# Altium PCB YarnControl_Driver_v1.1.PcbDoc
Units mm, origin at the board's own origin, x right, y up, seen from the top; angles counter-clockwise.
Board outline 80 x 60 mm, 2 copper layers (Top Layer, Bottom Layer); 133 components, 96 nets, 439 pads, 185 vias.
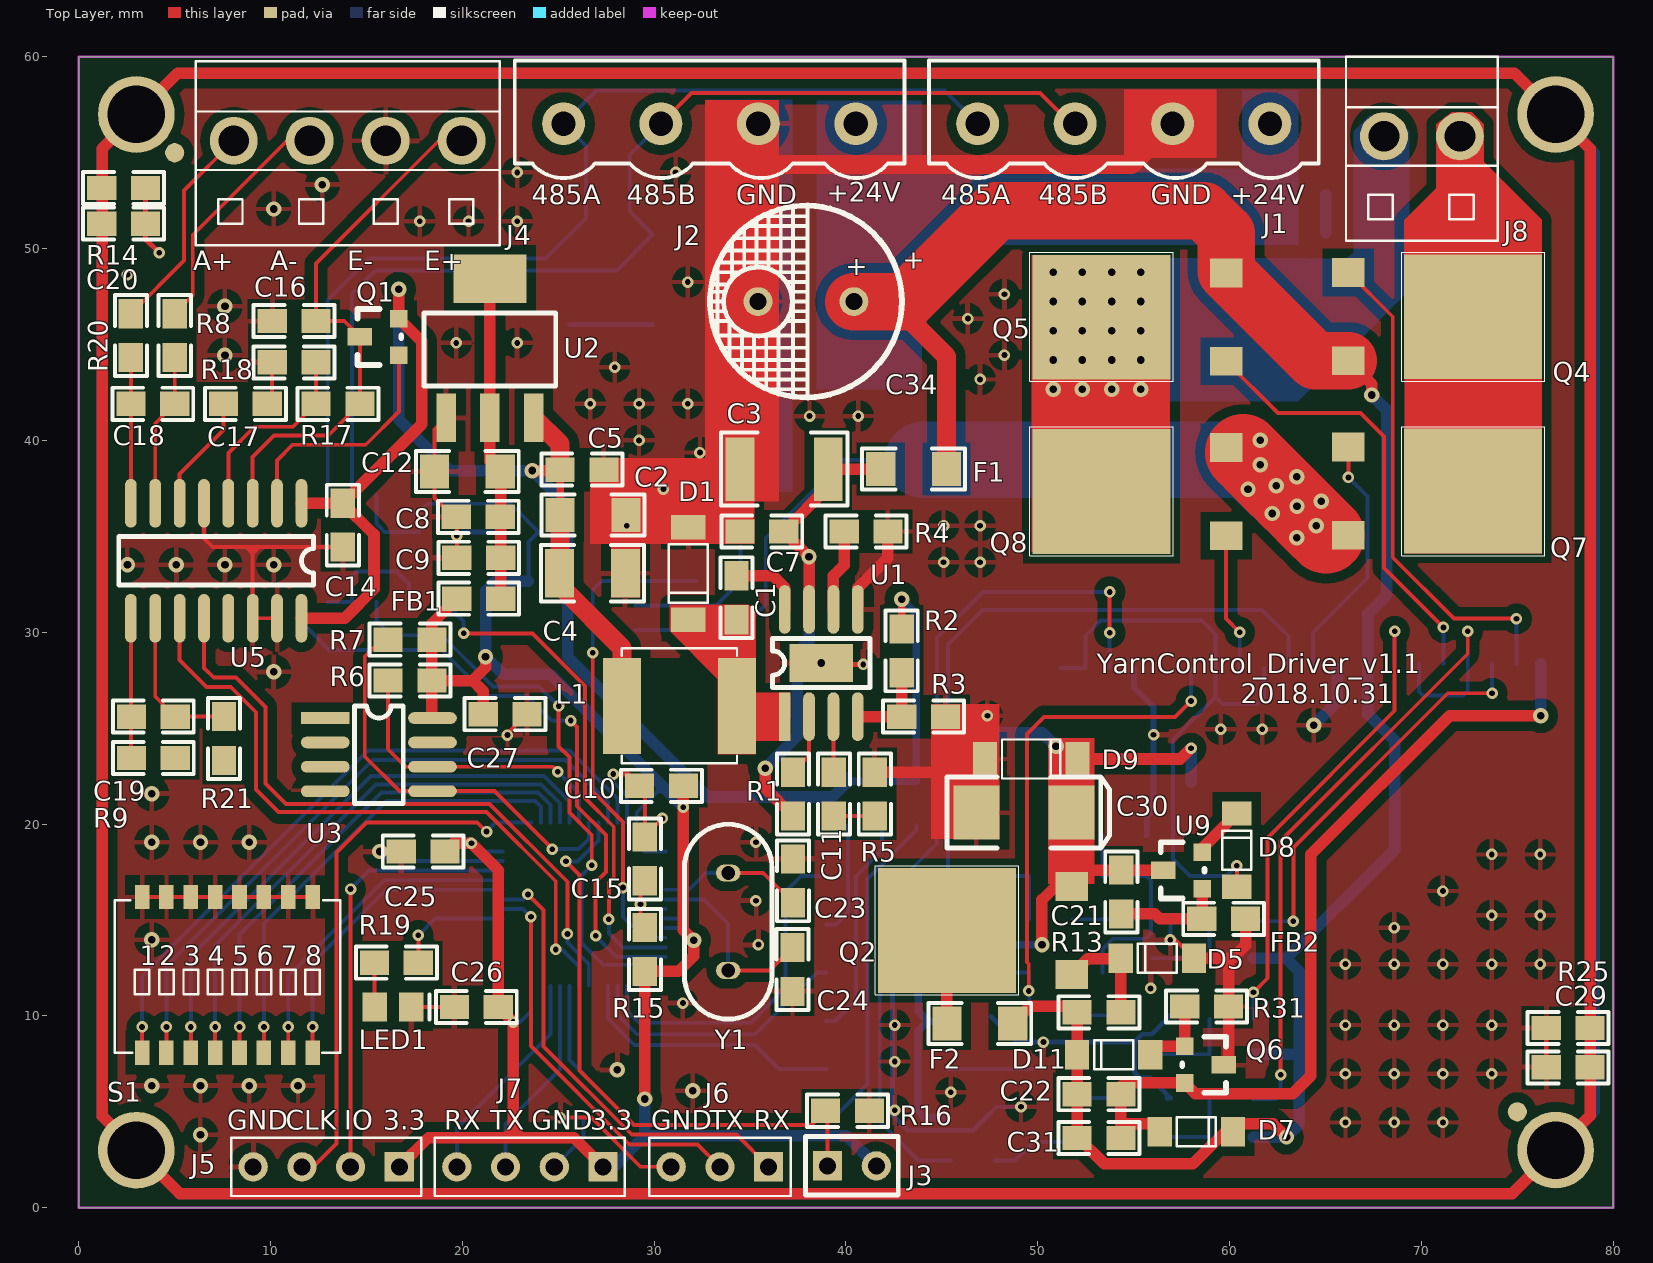
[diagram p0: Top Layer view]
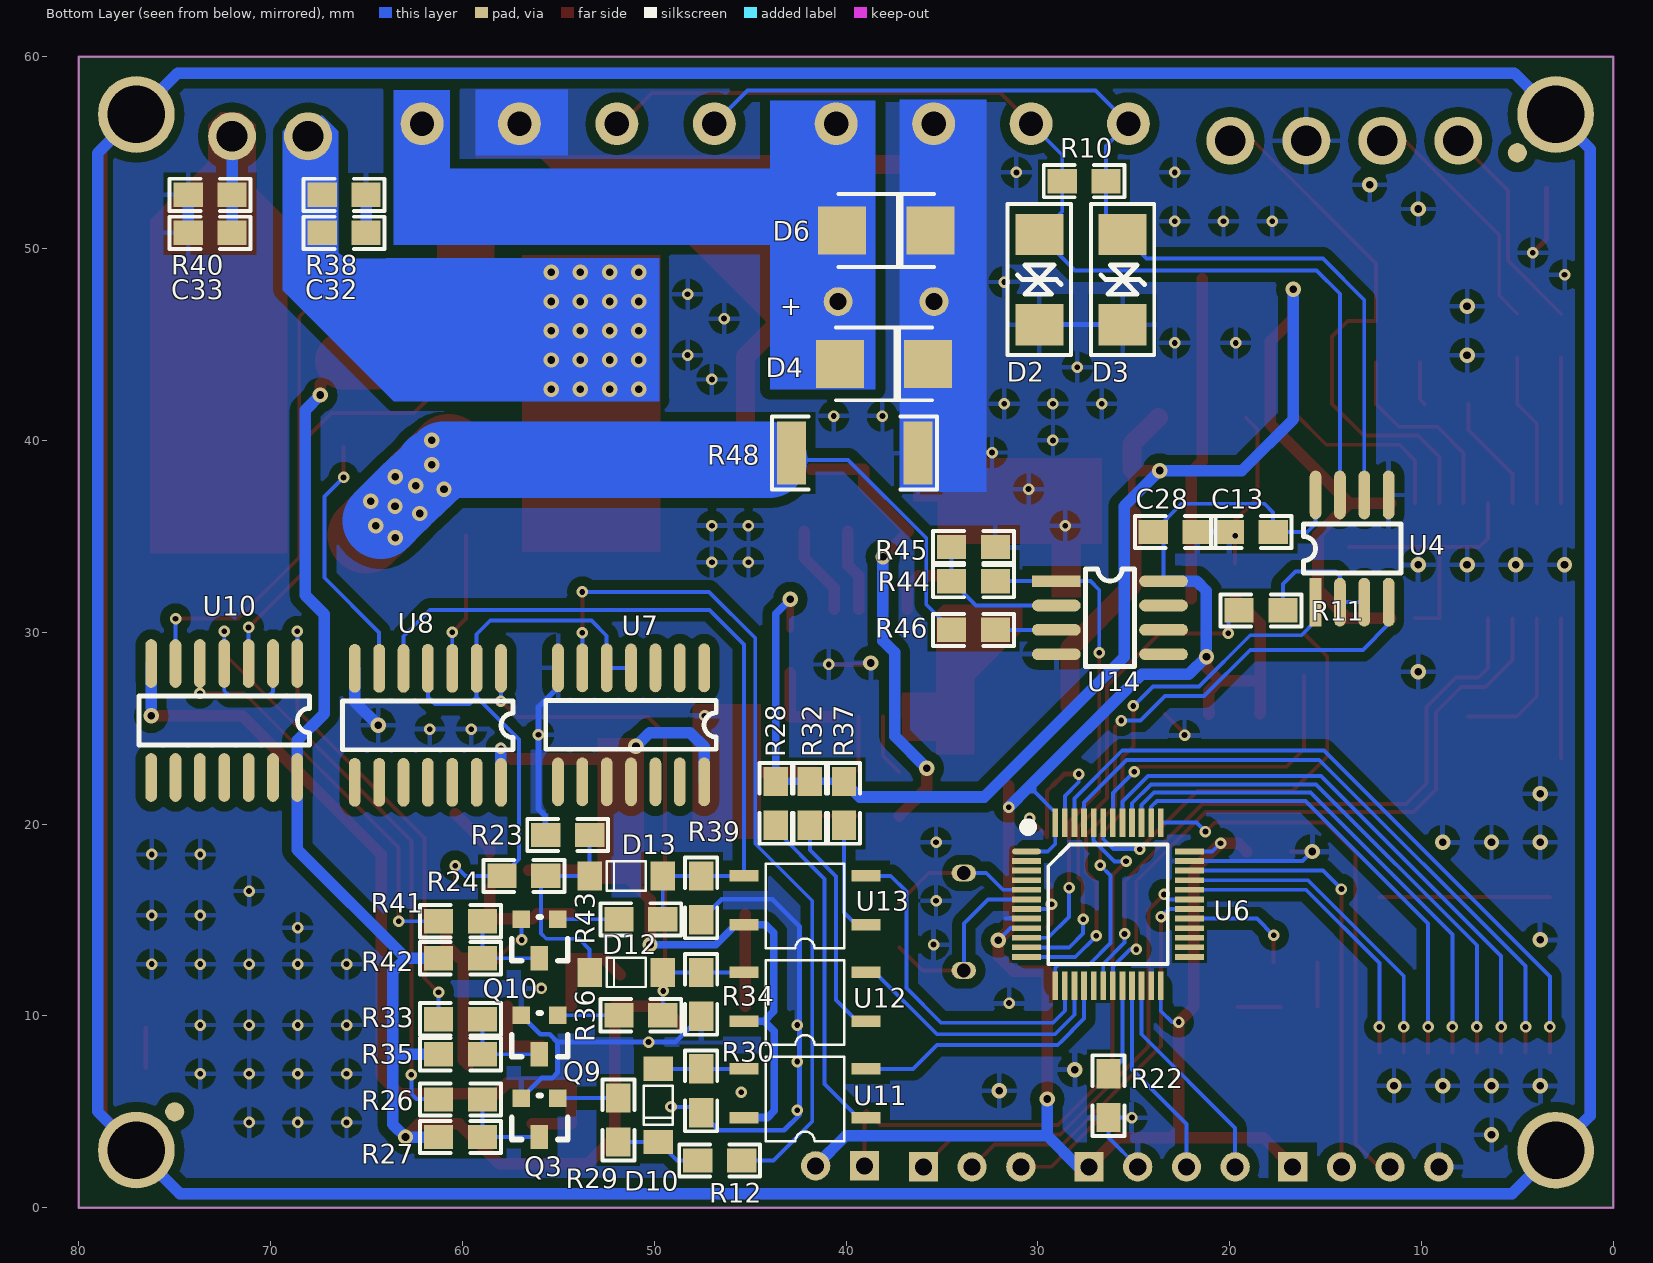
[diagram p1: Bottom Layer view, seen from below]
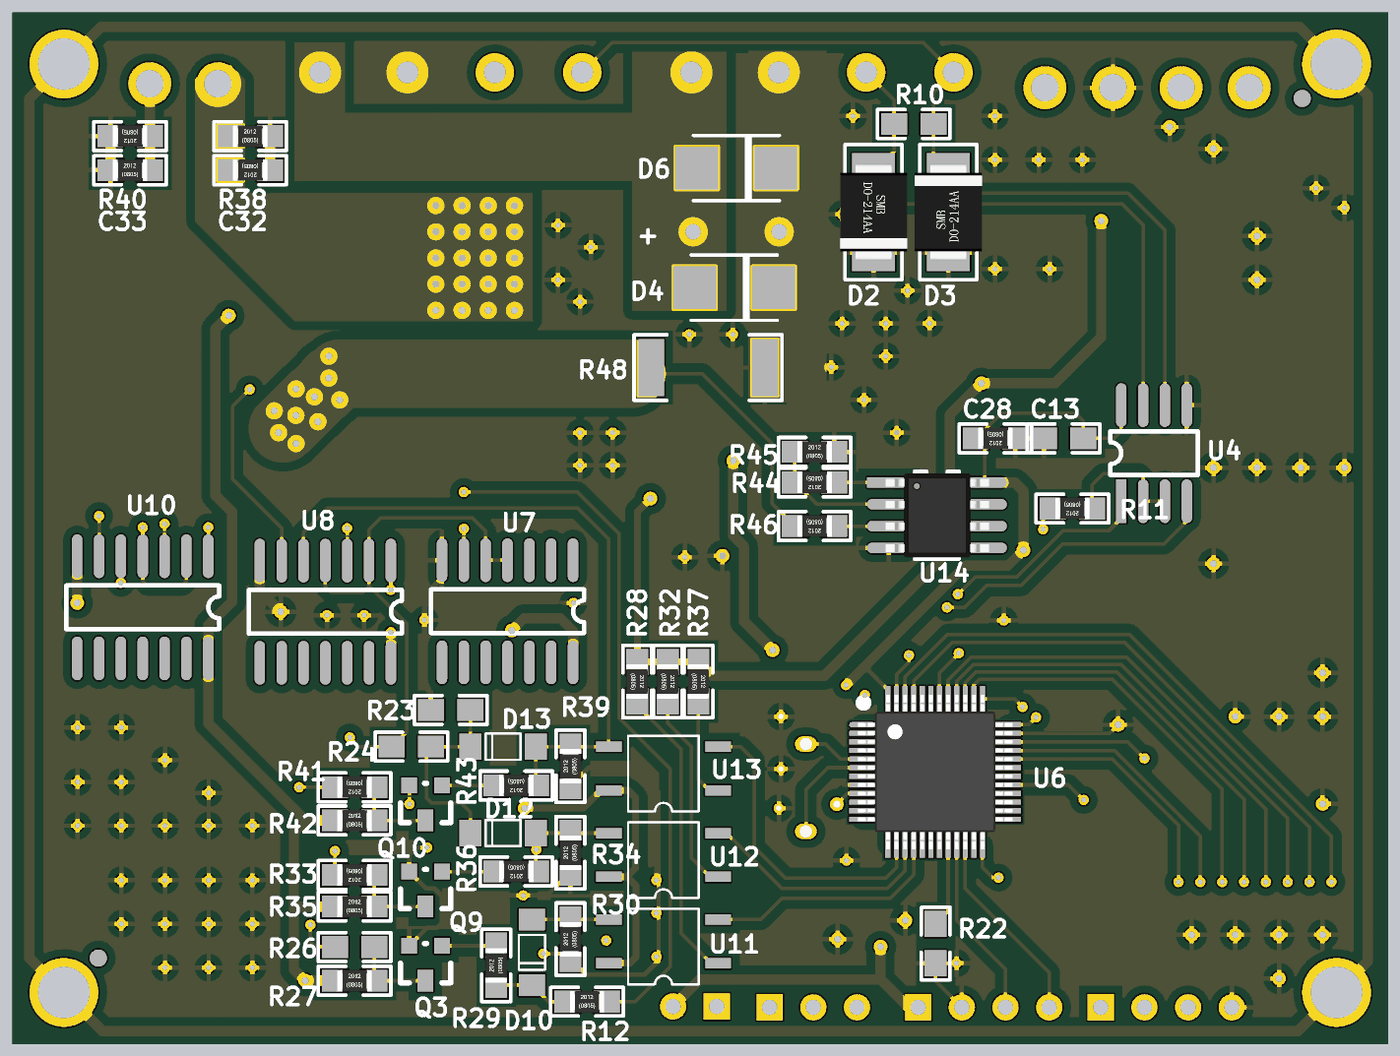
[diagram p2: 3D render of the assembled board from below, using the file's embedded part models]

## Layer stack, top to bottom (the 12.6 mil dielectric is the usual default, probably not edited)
Top Layer: signal copper 0.0356
Dielectric: dielectric 0.32, FR-4, Dk 4.8
Bottom Layer: signal copper 0.0356

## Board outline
0,0 80,0 80,60 0,60

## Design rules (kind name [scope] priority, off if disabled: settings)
Clearance LQFP_48 [(HasFootprint('LQFP_48'))] p1: gap=0.178
Clearance poly [inpoly] p2: gap=0.508
Clearance [All] p3: gap=0.203
Height [All] p1: minheight=0 maxheight=50 prefheight=12.7
HoleSize [All] p1: absolutevalues=TRUE maxlimit=4 minlimit=0.025 maxpercent=80.000 minpercent=20.000
MinimumSolderMaskSliver [All] p1: minsoldermaskwidth=0
PolygonConnect [All] p1: connectstyle=Relief reliefconductorwidth=0.254 reliefentries=4 polygonreliefangle="90 Angle"
RoutingVias [All] p1: holewidth=0.711 width=1.27 viastyle="Through Hole" minholewidth=0.3 minwidth=0.6 maxholewidth=0.711 maxwidth=1.27
SilkToSilkClearance [All] p1: silktosilkclearance=0
SilkscreenOverComponentPads [All] p1: minsilkscreentomaskgap=0
SolderMaskExpansion [All] p1: expansion=0.102
Width [All] p1: maxlimit=5 minlimit=0.203 preferedwidth=0.203
23 further rules are at their usual default settings.

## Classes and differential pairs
component class YarnControl_Driver_v1.1: C1 C2 C3 C4 C5 C7 C8 C9 C10 C11 C12 C13 C14 C15 C16 C17 C18 C19 C23 C24 C25 C26 C27 C28 D1 D2 D3 F1 FB1 J1 J2 J3 J4 J5 J6 J7 L1 LED1 Q1 R1 R2 R3 R4 R5 R6 R7 R8 R9 R10 R11 R15 R16 R17 R18 R19 R20 R21 R22 S1 U1 U2 U3 U4 U5 U6 Y1
component class YarnControl_motor_v1.1: C20 C21 C22 C29 C30 C31 C32 C33 C34 D4 D5 D6 D7 D8 D9 D10 D11 D12 D13 F2 FB2 J8 Q2 Q3 Q4 Q5 Q6 Q7 Q8 Q9 Q10 R12 R13 R14 R23 R24 R25 R26 R27 R28 R29 R30 R31 R32 R33 R34 R35 R36 R37 R38 R39 R40 R41 R42 R43 R44 R45 R46 R48 U7 U8 U9 U10 U11 U12 U13 U14

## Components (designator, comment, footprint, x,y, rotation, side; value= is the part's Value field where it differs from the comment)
C1 "0.1uF" 0805#1 34.29,32.944 r270 top
C2 "22uF" 1206 28.524,36.119 r180 top
C3 "47uF" 1812 36.779,38.506 r180 top
C4 "47uF" 1210 28.499,33.071 r180 top
C5 "0.1uF" 0805#1 27.381,38.481 r180 top
C7 "0.1uF" 0805#1 36.754,35.255 r180 top
C8 "10uF" 0805#1 19.685,36.017 r0 top
C9 "0.1uF" 0805#1 19.71,33.884 r0 top
C10 "0.1uF" 0805#2 30.378,21.996 r180 top
C11 "150pF" 0805#1 39.37,22.708 r270 top
C12 "22uF" 1206 21.971,38.379 r180 top
C13 "0.1uF" 0805#1 20.015,35.23 r180 bottom
C14 "1uF" 0805#1 13.767,34.442 r90 top
C15 "0.1uF" 0805#1 29.515,19.329 r270 top
C16 "1uF" 0805#1 10.084,46.228 r0 top
C17 "1uF" 0805#1 7.544,41.91 r0 top
C18 "0.1uF" 0805#1 5.004,41.91 r180 top
C19 "0.1uF" 0805#1 2.743,25.603 r0 top
C20 "10nF" 0805#2 2.337,51.308 r0 top
C21 "10uF" 0805#1 54.356,17.602 r270 top
C22 "10nF" 0805#1 52.045,5.918 r0 top
C23 "22pF" 0805#2 37.236,17.043 r270 top
C24 "22pF" 0805#2 37.211,12.421 r90 top
C25 "0.1uF" 0805#2 17.958,18.567 r0 top
C26 "0.1uF" 0805#2 20.726,10.465 r0 top
C27 "0.1uF" 0805#2 22.225,25.73 r180 top
C28 "0.1uF" 0805#2 22.835,35.23 r0 bottom
C29 "10nF" 0805#2 77.648,7.315 r180 top
C30 "100uF" CA6032-C 49.276,20.599 r0 top
C31 "22uF" 0805#2 53.188,3.632 r180 top
C32 "10nF" 0805#2 66.167,50.825 r0 bottom
C33 "10nF" 0805#2 73.152,50.825 r180 bottom
C34 "1000uF/35V" CAP-5MM 40.411,47.244 r180 top
D1 "1N5819" Diode_TP2 31.775,35.484 r270 top
D2 "SMBJ6.5CA" SMBJ_DO-214 29.921,48.387 r270 bottom
D3 "SMBJ6.5CA" SMBJ_DO-214 25.578,48.387 r90 bottom
D4 "SMCJ24A" DO-214AA/SMB 38.024,43.993 r180 bottom
D5 "ZMM6V2" DIDODE_LL-34 56.236,13.005 r180 top
D6 "SMCJ24A" DO-214AA/SMB 37.897,50.952 r180 bottom
D7 "ZMM6V2" DIDODE_LL-34 58.268,3.962 r0 top
D8 "1N4148" DIDODE_LL-34 60.376,18.644 r90 top
D9 "SMAJ5.0A" Diode_TP2 47.244,23.393 r0 top
D10 "1N4148" DIDODE_LL-34 49.784,5.334 r270 bottom
D11 "ZMM6V2" DIDODE_LL-34 53.95,7.976 r180 top
D12 "1N4148" DIDODE_LL-34 51.46,12.268 r0 bottom
D13 "1N4148" DIDODE_LL-34 51.46,17.297 r0 bottom
F1 "FUSE" 1206 45.237,38.506 r180 top
F2 "FUSE" 1206 45.263,9.601 r0 top
FB1 "FERRITE" 0805#1 21.996,31.75 r180 top
FB2 "FERRITE" 0805#2 59.69,15.062 r0 top
J1 "SH-4" J5.08_4(NoEar) 54.483,56.515 r180 top
J2 "SH-4" J5.08_4(NoEar) 32.893,56.515 r180 top
J3 "Jumper" J254-2 39.04,2.184 r0 top
J4 "SH-4" CH3.96-4P 14.021,55.626 r0 top
J5 "SH-4" J254-4 16.713,2.134 r180 top
J6 "SH-3" J2.54-3 33.426,2.134 r180 top
J7 "SH-4" J254-4 27.33,2.134 r180 top
J8 "SH-2" CH3.96-2P 70.028,55.855 r0 top
L1 "4.7uH" Inductance6*6 31.318,26.162 r180 top
LED1 "GREEN" LED 16.383,10.465 r0 top
Q1 "S8550" 901X_SOT-23 14.656,45.415 r90 top
Q2 "2SD1760" TO-252-2L 48.514,14.453 r90 top
Q3 "MMBT3904" SOT-23 55.982,3.683 r0 bottom
Q4 "NCE40P70K" TO-252 72.695,46.457 r270 top
Q5 "NCE40P70K" TO-252 53.315,46.431 r90 top
Q6 "MMBT2907A" 901X_SOT-23 59.69,7.442 r270 top
Q7 "NCE6075" TO-252 72.695,37.363 r270 top
Q8 "NCE6075" TO-252 53.315,37.338 r90 top
Q9 "MMBT3904" SOT-23 55.982,8.001 r0 bottom
Q10 "MMBT3904" SOT-23 55.982,13.005 r0 bottom
R1 "100K" 0805#1 37.236,22.708 r270 top
R2 "210K" 0805#1 42.901,30.175 r270 top
R3 "40.2K" 0805#1 45.187,25.603 r180 top
R4 "100K" 0805#1 42.189,35.255 r180 top
R5 "100K" 0805#1 41.504,22.708 r270 top
R6 "10K" 0805#1 16.129,27.483 r0 top
R7 "10K" 0805#1 16.129,29.616 r0 top
R8 "1K" 0805#2 5.004,45.466 r90 top
R9 "1K" 0805#2 3.886,23.444 r0 top
R10 "120R" 0805#1 28.727,53.518 r180 bottom
R11 "1K" 0805#2 18.364,31.14 r0 bottom
R12 "4.7K" 0805#2 46.584,2.464 r180 bottom
R13 "5.6K" 0805#2 53.188,10.185 r0 top
R14 "1M" 0805#2 2.337,53.162 r180 top
R15 "10K" 0805#1 29.515,14.605 r270 top
R16 "10K" 0805#1 38.938,5.055 r0 top
R17 "20K" 0805#1 12.37,41.91 r0 top
R18 "8.2K" 0805#1 12.37,44.069 r180 top
R19 "1K" 0805#1 15.418,12.776 r0 top
R20 "1K" 0805#1 2.718,44.323 r90 top
R21 "1K" 0805#1 7.569,25.603 r270 top
R22 "10K" 0805#1 26.314,4.699 r90 bottom
R23 "10K" 0805#1 55.651,19.431 r180 bottom
R24 "10K" 0805#1 55.651,17.297 r0 bottom
R25 "1M" 0805#1 76.505,9.373 r0 top
R26 "10K" 0805#1 58.953,5.639 r0 bottom
R27 "10K" 0805#2 60.096,3.683 r180 bottom
R28 "510R" 0805#2 43.663,21.082 r270 bottom
R29 "10K" 0805#2 51.867,4.572 r90 bottom
R30 "510R" 0805#2 47.549,6.096 r90 bottom
R31 "5.6K" 0805#2 58.801,10.49 r180 top
R32 "510R" 0805#2 41.885,21.082 r270 bottom
R33 "10K" 0805#2 60.096,9.83 r0 bottom
R34 "4.7K" 0805#2 47.549,11.125 r90 bottom
R35 "10K" 0805#2 60.096,8.001 r180 bottom
R36 "10K" 0805#2 50.698,10.033 r0 bottom
R37 "510R" 0805#2 40.107,21.082 r270 bottom
R38 "1M" 0805#2 66.167,52.807 r180 bottom
R39 "4.7K" 0805#2 47.549,16.154 r90 bottom
R40 "1M" 0805#2 73.152,52.807 r0 bottom
R41 "10K" 0805#2 60.096,14.935 r0 bottom
R42 "10K" 0805#2 60.096,13.005 r180 bottom
R43 "10K" 0805#2 50.698,15.037 r0 bottom
R44 "10K" 0805#2 33.35,32.664 r0 bottom
R45 "1K" 0805#2 33.35,34.442 r180 bottom
R46 "1K" 0805#2 33.35,30.124 r0 bottom
R48 "R100" 2512 39.548,39.345 r0 bottom
S1 "SW-CH8" SWITCH_8 7.747,12.141 r0 top
U1 "MP1584" MP1584 38.71,28.397 r90 top
U2 "AMS1117" TO-223 21.438,44.806 r0 top
U3 "SMEC98SP" SO-8#1 15.646,23.622 r0 top
U4 "SP3485" SO-8#1 13.614,34.366 r90 bottom
U5 "HX711" SO-16 11.608,36.728 r270 top
U6 "STM32F103C8T6" LQFP_48 26.34,15.824 r180 bottom
U7 "74VHC00" SO-14 47.396,28.143 r270 bottom
U8 "74VHC08" SO-14 57.988,28.118 r270 bottom
U9 "MAX809" SOT-23 56.54,17.602 r90 top
U10 "74VHC00" SO-14 68.605,28.372 r270 bottom
U11 "EL357N" EL357N 42.139,5.969 r0 bottom
U12 "EL357N" EL357N 42.139,10.998 r0 bottom
U13 "EL357N" EL357N 42.139,16.027 r0 bottom
U14 "LM358" SO-8#2 29.032,32.664 r180 bottom
Y1 "8M" XTAL 33.858,12.37 r90 top

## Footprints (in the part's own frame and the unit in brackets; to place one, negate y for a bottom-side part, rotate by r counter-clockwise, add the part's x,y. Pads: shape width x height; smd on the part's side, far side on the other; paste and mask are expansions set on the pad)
0805#1 [mil]
  rect 60x50 smd: 1(0,0) 2(90,0)
  silkscreen extent -38,-33 128,33
0805#2 [mil]
  rect 60x50 smd: 1(-45,0) 2(45,0)
  silkscreen extent -83,-33 83,33, body extent -39,-25 39,24, height 18
901X_SOT-23 [mil]
  rect 36x50 smd: 1(0,0)
  rect 36x36 smd: 2(-38,-80) 3(37,-80)
  silkscreen extent -58,-85 57,5
1206 [mil]
  rect 60x70 smd: 1(0,0) 2(135,0)
  silkscreen extent -38,-42 173,42
1210 [mil]
  rect 60x100 smd: 1(0,0) 2(135,0)
  silkscreen extent -38,-58 173,58
1812 [mm]
  rect 1.5x3.3 smd: 1(-2.3,0) 2(2.3,0)
  silkscreen extent -3.3,-1.91 3.3,1.91
2512 [mm]
  rect 1.5x3.3 smd: 1(-3.3,0) 2(3.3,0)
  silkscreen extent -4.3,-1.91 4.3,1.91
CA6032-C [mm]
  rect 2.4x2.8 smd: 1(2.48,0) 2(-2.48,0)
  silkscreen extent -4.01,-1.85 4.47,1.85, body extent -3.05,-1.68 3.05,1.67, height 2.7
CAP-5MM [mm]
  round 1.5 hole 0.9: 1(0,0) 2(5,0)
  silkscreen extent -2.5,-5 7.5,5
CH3.96-2P [mm]
  round 2.5 hole 1.6: 1(-1.98,0) 2(1.98,0)
  silkscreen extent -3.96,-5.45 3.96,4.15
CH3.96-4P [mm]
  round 2.5 hole 1.6: 1(-5.94,0) 2(-1.98,0) 3(1.98,0) 4(5.94,0)
  silkscreen extent -7.92,-5.45 7.92,4.15
DIDODE_LL-34 [mil]
  rect 50x60 smd: 1(-75,0) 2(75,0)
  silkscreen extent -40,-30 40,30
Diode_TP2 [mil]
  rect 50x70 smd: 1(0,0) 2(190,0)
  silkscreen extent 35,-40 155,40
DO-214AA/SMB [mm]
  rect 2.5x2.5 smd: 1(-2.3,0) 2(2.3,0)
  silkscreen extent -2.5,-1.9 2.5,1.9
EL357N [mm]
  rect 1.5x0.6 smd: 1(-3.175,1.27) 2(-3.175,-1.27) 3(3.175,-1.27) 4(3.175,1.27)
  silkscreen extent -2.05,-1.9 2.05,2.5
Inductance6*6 [mm]
  rect 2x5 smd: 1(-3,0) 2(3,0)
  silkscreen extent -3,-3 3,3
J2.54-3 [mil]
  rect 60x60 hole 35: 1(-100,0)
  round 60 hole 35: 2(0,0) 3(100,0)
  silkscreen extent -145,-60 145,60
J5.08_4(NoEar) [mil]
  round 88 hole 50: 1(300,0) 2(100,0) 3(-100,0) 4(-300,0)
  silkscreen extent -400,-130 400,111
J254-2 [mil]
  rect 60x60 hole 35: 1(0,0)
  round 60 hole 35: 2(100,0)
  silkscreen extent -45,-60 145,60
J254-4 [mil]
  rect 60x60 hole 35: 1(0,0)
  round 60 hole 35: 2(100,0) 3(200,0) 4(300,0)
  silkscreen extent -45,-60 345,60
LED [mm]
  rect 1.3x1.5 smd: 1(-0.95,0) 2(0.95,0)
  silkscreen extent 1.9,-0.65 1.9,0.65
LQFP_48 [mm]
  oval 1.5x0.3 smd: 1(-4.25,2.75)
  rect 1.5x0.3 smd: 2(-4.25,2.25) 3(-4.25,1.75) 4(-4.25,1.25) 5(-4.25,0.75) 6(-4.25,0.25) 7(-4.25,-0.25) 8(-4.25,-0.75) 9(-4.25,-1.25) 10(-4.25,-1.75) 11(-4.25,-2.25) 12(-4.25,-2.75) 25(4.25,-2.75) 26(4.25,-2.25) 27(4.25,-1.75) 28(4.25,-1.25) 29(4.25,-0.75) 30(4.25,-0.25) 31(4.25,0.25) 32(4.25,0.75) 33(4.25,1.25) 34(4.25,1.75) 35(4.25,2.25) 36(4.25,2.75)
  rect 0.3x1.5 smd: 13(-2.75,-4.25) 14(-2.25,-4.25) 15(-1.75,-4.25) 16(-1.25,-4.25) 17(-0.75,-4.25) 18(-0.25,-4.25) 19(0.25,-4.25) 20(0.75,-4.25) 21(1.25,-4.25) 22(1.75,-4.25) 23(2.25,-4.25) 24(2.75,-4.25) 37(2.75,4.25) 38(2.25,4.25) 39(1.75,4.25) 40(1.25,4.25) 41(0.75,4.25) 42(0.25,4.25) 43(-0.25,4.25) 44(-0.75,4.25) 45(-1.25,4.25) 46(-1.75,4.25) 47(-2.25,4.25) 48(-2.75,4.25)
  silkscreen extent -4.33,-3.11 3.11,4.18, body extent -4.5,-4.5 4.5,4.5, height 1.6
MP1584 [mil]
  rect 78.74x129.92 smd: 0(0,0)
  rect 100x24 smd: 1(-110,75)
  oval 100x24 smd: 2(-110,25) 3(-110,-25) 4(-110,-75) 5(110,-75) 6(110,-25) 7(110,25) 8(110,75)
  silkscreen extent -50,-100 50,100
SMBJ_DO-214 [mm]
  rect 2.16x2.5 smd: 1(-2.35,0) 2(2.35,0)
  silkscreen extent -3.94,-1.65 3.94,1.65, body extent -2.8,-1.95 2.8,1.95, height 2.5
SO-8#1 [mil]
  rect 100x24 smd: 1(-110,75)
  oval 100x24 smd: 2(-110,25) 3(-110,-25) 4(-110,-75) 5(110,-75) 6(110,-25) 7(110,25) 8(110,75)
  silkscreen extent -50,-100 50,100
SO-8#2 [mil]
  rect 100x24 smd: 1(0,0)
  oval 100x24 smd: 2(0,-50) 3(0,-100) 4(0,-150) 5(220,-150) 6(220,-100) 7(220,-50) 8(220,0)
  silkscreen extent 60,-175 160,25, body extent -7,-172 229,21, height 67
SO-14 [mil]
  oval 100x24 smd: 1(0,0) 2(0,-50) 3(0,-100) 4(0,-150) 5(0,-200) 6(0,-250) 7(0,-300) 8(234,-300) 9(234,-250) 10(234,-200) 11(234,-150) 12(234,-100) 13(234,-50) 14(234,0)
  silkscreen extent 67,-325 167,25
SO-16 [mil]
  oval 100x24 smd: 1(0,0) 2(0,-50) 3(0,-100) 4(0,-150) 5(0,-200) 6(0,-250) 7(0,-300) 8(0,-350) 9(236,-350) 10(236,-300) 11(236,-250) 12(236,-200) 13(236,-150) 14(236,-100) 15(236,-50) 16(236,0)
  silkscreen extent 68,-375 168,25
SOT-23 [mil]
  rect 36x36 smd: 1(-38,-80) 2(37,-80)
  rect 36x50 smd: 3(0,0)
  silkscreen extent -58,-85 57,5
SWITCH_8 [mm]
  rect 0.76x1.27 smd: 1(-4.445,-4.06) 2(-3.175,-4.06) 3(-1.905,-4.06) 4(-0.635,-4.06) 5(0.635,-4.06) 6(1.905,-4.06) 7(3.175,-4.06) 8(4.445,-4.06) 9(4.445,4.06) 10(3.175,4.06) 11(1.905,4.06) 12(0.635,4.06) 13(-0.635,4.06) 14(-1.905,4.06) 15(-3.175,4.06) 16(-4.445,4.06)
  silkscreen extent -5.88,-4.06 5.88,3.88
TO-223 [mil]
  rect 150x100 smd: 0(0,142.5)
  rect 40x100 smd: 1(-90,-142.5) 2(0,-142.5) 3(90,-142.5)
  silkscreen extent -135,-78 135,72
TO-252 [mm]
  rect 6.5x7.2 smd: 1(0,0)
  rect 1.5x1.7 smd: 2(-2.3,-6.5) 3(2.3,-6.5)
  silkscreen extent -3.35,-3.73 3.38,3.73
TO-252-2L [mm]
  rect 1.5x1.7 smd: 1(-2.3,-3.25) 3(2.3,-3.25)
  rect 6.5x7.2 smd: 2(0,3.25)
  silkscreen extent -3.35,-0.48 3.38,6.98
XTAL [mil]
  oval 35x50 hole 28: 1(0,0) 2(200,0)
  silkscreen extent -100,-90 300,90, body extent -121,-93 319,91, height 143

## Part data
C1 C2 C3 C7 C11 C12 C14 C16 C17 C18 C19 C20 C21 C22 C23 C24 C29 C31 C32 C33: library part CAP, "电容"
C4 C5 C8 C9: library part Cap0805
C10 C13 C15 C25 C26 C27 C28: library part Cap, "Capacitor"
C30: library part CapAEC*4
C34: library part "Cap Pol1", "Polarized Capacitor (Radial)"
D1: library part Diode, "二极管"
D2 D3 D4 D6 D9: library part TVS
D5 D7 D11: library part "D Zener", "Zener Diode"
D8 D10 D12 D13: library part Diode, "Default Diode"
F1 F2: "保险丝"
L1: library part Inductor, "电感"
LED1: library part LED2, "Typical RED, GREEN, YELLOW, AMBER GaAs LED"
Q1 Q6: library part PNP
Q3 Q9 Q10: library part S8050
Q4 Q5: library part MOSFET-P, "P-Channel MOSFET"
Q7 Q8: library part MOSFET-N, "N-Channel MOSFET"
R1 R2 R3 R4 R5 R8 R9 R12 R13 R14 R16 R17 R18 R19 R20 R21 R23 R24 R25 R26 R27 R28 R29 R30 R31 R32 R33 R34 R35 R36 R37 R38 R39 R40 R41 R42 R43 R44 R45 R46 R48: library part RES, "电阻"
R6 R7 R10 R11 R15 R22: library part Res2, "Resistor"
S1: "拨码开关CH8"
U4: "485"
U8: library part 74HC08
U11 U12 U13: library part TLP521
Y1: library part XTAL, "Crystal Oscillator"

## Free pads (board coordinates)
  round 4 hole 3: 0(3,3) 0(3,57) 0(77,3) 0(77,57)
  round 1 smd: 0(5,55) 0(75,5)
  round 1 smd far side: 0(5,55) 0(75,5)

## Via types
v1: diameter 0.6, hole 0.3, Top Layer to Bottom Layer, 118 vias
v2: diameter 0.8, hole 0.4, Top Layer to Bottom Layer, 67 vias

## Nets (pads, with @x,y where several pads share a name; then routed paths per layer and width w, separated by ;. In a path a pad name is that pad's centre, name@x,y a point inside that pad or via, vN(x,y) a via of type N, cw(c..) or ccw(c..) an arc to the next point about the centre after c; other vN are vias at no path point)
485_DE: R11.2 U6.11 | length 25.8
  Top Layer w0.203: v1(20.066,29.947) 23.647,29.947 26.391,27.203 26.391,21.361 27.889,19.863 27.889,17.221 27.635,16.967 v1(27.635,15.037)
  Bottom Layer w0.203: R11.2 20.066,30.582 v1(20.066,29.947) ; v1(27.635,15.037) 27.635,14.3 28.361,13.574 U6.11
485_RX: U4.1 U6.13 | length 30
  Top Layer w0.203: v1(25.019,26.162) 25.019,24.054 25.578,23.495 25.578,20.599 26.746,19.431 v1(26.746,17.856)
  Bottom Layer w0.203: U4.1 15.519,30.582 16.256,29.845 18.923,29.845 21.59,27.178 24.003,27.178 v1(25.019,26.162) ; v1(26.746,17.856) 26.213,17.323 26.213,13.792 27.337,12.668 28.912,12.668 29.09,12.49 U6.13
485_TX: U4.4 U6.12 | length 33.5
  Top Layer w0.203: v1(25.654,25.4) 25.984,25.07 25.984,20.93 27.483,19.431 27.483,17.501 26.949,16.967 v1(26.949,14.173)
  Bottom Layer w0.203: U4.4 11.709,30.429 13.056,29.083 18.923,29.083 21.336,26.67 23.368,26.67 24.638,25.4 v1(25.654,25.4) ; v1(26.949,14.173) 28.048,13.074 U6.12
+3.3V: C10.1 C13.2 C25.2 C26.2 C27.2 C28.2 FB1.2 J3.2 J5.1 J7.1 R6.2 R7.2 R15.2 U3.8 U4.8 U6.1 U6.9 U6.24 U6.36 U6.48 U14.8 | length 125.1
  Top Layer w0.203: U3.8@18.415,25.756 U3.8@18.44,25.73 ; C27.2 C27.2@21.26,25.73
  Top Layer w0.6: J5.1 18.237,3.658 22.276,3.658 ; R7.2@18.415,29.947 R7.2 ; U3.8@18.44,25.756 18.415,25.756 R6.2 ; C25.2 19.533,18.999 v1(20.472,18.999) 21.869,17.602 C26.2 v1(22.657,9.677) 22.657,4.039 ; FB1.2 18.415,30.455 R7.2 ; C27.2@21.057,25.756 C27.2 21.082,26.924 20.523,27.483 ; v2(21.209,28.727) 21.209,28.169 20.523,27.483 ; 23.038,3.658 22.657,4.039 ; J7.1 25.806,3.658 22.276,3.658 ; v2(29.515,5.664) R15.2 31.267,12.319 32.055,13.106 v2(32.055,13.945) 31.521,14.478 v1(31.521,20.879) C10.1 ; R6.2 R7.2 ; R6.2 20.523,27.483 ; 22.276,3.658 22.657,4.039
  Bottom Layer w0.203: U4.8 15.519,35.662 15.951,35.23 C13.2 17.729,36.246 18.186,36.703 22.504,36.703 C28.2 23.444,34.696 U14.8 ; v1(20.472,18.999) 20.904,18.567 U6.36@22.083,18.567 ; 23.012,9.677 23.59,10.255 U6.24 ; 30.175,22.186 30.175,21.692 ; 30.455,21.971 30.442,21.958 30.175,21.692 ; U6.9 31.425,14.574 v2(32.055,13.945) ; U6.1 29.483,18.574 29.09,18.967 U6.48 29.09,20.606 30.175,21.692 ; 30.658,21.692 30.175,21.692
  Bottom Layer w0.6: U14.8 21.717,32.664 21.209,32.156 v2(21.209,28.727) 22.123,27.813 24.587,27.813 30.442,21.958 v1(31.521,20.879) ; J7.1 27.889,2.134 29.515,3.759 40.005,3.759 J3.2 ; 29.515,3.937 v2(29.515,5.664)
+5V: C2.2 C4.2 C5.2 C14.2 L1.2 Q1.3 R2.1 R28.1 R32.1 R37.1 U2.3 U5.1 U5.16 | length 105
  Top Layer w0.4: C5.2@24.765,38.481 C5.2 C2.2 C4.2@25.095,33.376 ; L1.2 L1.2@28.321,26.165 ; R2.1 v2(42.901,31.725)
  Top Layer w0.6: U5.16 13.868,30.734 15.392,32.258 15.392,35.103 C14.2 ; U5.1 C14.2 ; v2(16.688,47.879) Q1.3 17.882,45.161 17.882,40.843 C14.2 ; v2(23.647,38.43) 25.044,38.43 C5.2
  Top Layer w1: U2.3 25.095,39.814 C5.2 ; C2.2 25.095,32.408 28.318,29.185 L1.2
  Bottom Layer w0.4: R37.1@40.107,22.504 R37.1 R32.1 R28.1 43.663,30.963 v2(42.901,31.725)
  Bottom Layer w0.6: v2(16.688,47.879) 16.688,41.097 19.355,38.43 v2(23.647,38.43) 25.502,36.576 25.502,28.702 32.791,21.412 39.294,21.412 R37.1
+24V: C22.1 C31.2 C34.1 D4.1 D6.1 D7.2 D11.2 F1.1 F2.2 J1.4 J2.4 Q4.3 Q5.3 R13.1 R27.1 R35.1 R42.1 U10.14 | length 118.2
  Top Layer w0.6: F2.2 49.581,10.49 52.045,10.49 52.045,3.708 53.467,2.286 58.09,2.286 60.173,4.369 62.281,4.369 v2(62.967,3.683) ; Q4.3 67.412,42.94 v2(67.412,42.367)
  Top Layer w1: C34.1 42.367,47.244 45.237,44.374 F1.1
  Top Layer w3: C34.1 43.104,47.244 47.828,51.968 58.649,51.968 59.815,50.802 59.815,48.796 64.454,44.157 Q4.3
  Bottom Layer w0.6: R27.1 v2(62.967,3.683) 63.627,4.343 63.627,7.976 ; R35.1 63.602,8.001 63.627,7.976 ; R42.1 62.941,13.005 ; v2(67.412,42.367) 68.199,41.58 68.199,31.928 67.208,30.937 67.208,25.756 68.605,24.359 U10.14 68.605,18.669 62.941,13.005 ; 62.941,13.005 63.627,12.319 63.627,7.976
BOOT0: J3.1 R16.1 U6.44 | length 31.5
  Top Layer w0.203: v1(25.4,18.059) 26.111,17.348 26.111,7.163 28.956,4.318 38.202,4.318 R16.1 39.04,4.953 J3.1
  Bottom Layer w0.203: v1(25.4,18.059) 26.01,18.059 27.09,19.14 U6.44
BOOT1: R22.2 U6.20 | length 4.9
  Bottom Layer w0.203: U6.20 25.59,7.71 R22.2
BT_RXD: J7.4 U6.22 | length 11.5
  Bottom Layer w0.203: J7.4 19.71,4.166 24.59,9.045 U6.22
BT_TXD: J7.3 U6.21 | length 10.6
  Bottom Layer w0.203: J7.3 22.25,4.369 25.09,7.208 U6.21
EARTH: C20.1 C29.1 pad.0@3,3 pad.0@3,57 pad.0@77,3 pad.0@77,57 R14.2 R25.2 | length 525.5
  Top Layer w0.6: 1.219,4.781 1.219,55.219 3,57 5.156,59.157 74.843,59.157 78.791,55.209 78.791,4.791 74.737,0.737 5.263,0.737 1.219,4.781
  Bottom Layer w0.6: 1.194,4.806 1.194,55.194 5.157,59.157 74.843,59.157 79.019,54.981 79.019,5.019 74.737,0.737 5.263,0.737 3,3 1.194,4.806
ENA: U6.16 U11.2 | length 15.9
  Bottom Layer w0.203: U6.16 27.59,9.854 ; 28.8,8.644 27.59,9.854 ; U11.2 36.5,7.239 35.255,8.484 28.96,8.484 27.59,9.854
GND: C2.1 C3.2 C4.1 C5.1 C7.2 C8.1 C9.1 C10.2 C12.2 C13.1 C14.1 C15.1 C16.1 C17.2 C20.2 C23.1 C24.1 C25.1 C26.1 C27.1 C28.1 C29.2 C30.2 C32.1 C33.1 C34.2 D1.1 D2.2 D3.1 D4.2 D5.1 D6.2 D9.1 FB2.2 J1.3 J2.3 J4.3 J5.4 J6.3 J7.2 LED1.2 Q3.2 Q6.1 Q9.2 Q10.2 R3.1 R4.1 R5.1 R14.1 R16.2 R18.2 R22.1 R23.1 R25.1 R30.1 R31.1 R34.1 R38.2 R39.1 R40.2 R45.2 R48.1 S1.9 S1.10 S1.11 S1.12 S1.13 S1.14 S1.15 S1.16 U1.0 U1.5 U2.1 U3.4 U4.5 U5.5 U5.14 U5.15 U6.8 U6.23 U6.35 U6.47 U7.7 U8.7 U14.4 | length 198.2
  Top Layer w0.203: S1.16 S1.15 S1.14 S1.13 S1.12 S1.11 S1.10 S1.9 ; U5.5 6.528,34.9 6.985,34.442 8.738,34.442 ; C17.2 10.084,42.164 R18.2 ; U5.15 U5.14 9.068,34.112 ; C14.1 9.398,34.442 ; v2(15.697,18.567) C25.1 ; LED1.2 C26.1 ; U2.1 18.542,40.576 C12.2 18.542,37.008 19.609,35.941 19.71,35.839 v1(19.71,35.027) C9.1 C9.1@19.71,33.579 ; v1(22.352,24.638) 22.352,24.714 C27.1 ; J7.2@24.79,1.549 J7.2 ; v1(25.095,4.699) 26.73,4.699 29.296,2.134 J6.3 J6.3@30.886,1.549 ; C5.1@27.851,38.951 28.524,38.278 C2.1 28.524,35.56 28.524,33.401 C4.1@28.499,33.376 ; C10.2 29.515,21.717 C15.1@29.515,19.38 ; C15.1 C15.1@29.515,19.38 ; v1(30.429,20.295) C15.1@29.515,19.38 ; C7.2@34.265,35.255 C7.2 C3.2@34.468,37.414 ; v1(56.909,13.957) 57.188,13.957 D5.1 ; 8.738,34.442 9.068,34.112 ; 8.738,34.442 9.068,34.442 ; 9.068,34.112 9.068,34.442 ; 9.068,34.112 9.398,34.442 ; 9.068,34.442 9.398,34.442
  Top Layer w0.254: R14.1 C20.2 3.48,50.495 v1(4.191,49.784) ; v1(27.864,22.606) 28.626,22.606 C10.2 ; U1.0@38.786,28.321 v1(40.894,28.321) ; C29.2 R25.1
  Top Layer w0.6: U1.5 40.615,32.309 42.189,33.884 R4.1 ; R5.1@41.605,22.708 44.933,22.708 45.187,22.962 R3.1 ; D5.1 60.147,13.005 60.833,13.691 FB2.2 ; Q6.1 59.944,7.696 R31.1 59.944,12.802
  Top Layer w1: 34.468,54.635 34.722,54.381 54.889,54.381 J1.3 ; R3.1 46.796,23.994 46.796,23.393 C30.2
  Bottom Layer w0.203: v2(15.697,18.567) 16.19,18.074 U6.35 ; J7.2 26.314,3.658 R22.1 v1(25.095,4.699) ; v1(27.864,22.606) 27.864,22.2 28.59,21.474 U6.47 ; U6.8 31.687,15.074 ; R30.1 47.854,5.258 v1(49.124,5.258) ; v1(56.909,13.957) 56.909,15.024 Q10.2
  Bottom Layer w0.254: C13.1 C28.1 ; D3.1 D2.2 ; R30.1 46.634,4.039 43.231,4.039 42.418,4.851 42.418,5.08 42.418,7.62 42.418,9.525 42.418,14.656 43.84,16.078 46.482,16.078 R39.1 ; R34.1 48.895,8.636 v1(50.292,8.636) 55.042,8.636 ; Q9.2@56.744,10.033 Q9.2 55.931,9.042 55.448,9.042 55.042,8.636 ; Q3.2@56.744,5.715 Q3.2 55.88,6.756 55.321,6.756 55.042,7.036 55.042,8.636
  Bottom Layer w0.3: U7.7 55.016,27.127 56.032,26.111 v1(56.032,24.663) 56.032,20.777 55.677,20.422 55.677,19.456 R23.1
  Bottom Layer w0.6: v2(64.389,25.146) 65.608,26.365 U8.7 ; C32.1 R38.2 ; C33.1 R40.2
  other v1: 66.04,4.445 68.58,4.445 71.12,4.445 42.545,5.08 45.466,6.02 66.04,6.985 68.58,6.985 71.12,6.985 73.66,6.985 42.545,7.62 42.545,9.525 66.04,9.525 68.58,9.525 71.12,9.525 73.66,9.525 31.496,10.668 55.88,11.43 66.04,12.7 68.58,12.7 71.12,12.7 73.66,12.7 76.2,12.7 35.433,13.716 68.58,14.605 73.66,15.24 76.2,15.24 35.306,16.002 71.12,16.51 73.66,18.415 76.2,18.415 35.306,19.05 59.538,24.943 61.697,24.943 47.371,25.654 45.085,33.655 46.99,33.655 28.575,35.56 45.085,35.56 46.99,35.56 30.48,37.465 32.385,39.37 29.21,40.005 38.1,41.275 40.64,41.275 26.67,41.91 29.21,41.91 31.75,41.91 46.99,43.18 27.94,43.815 48.26,44.45 19.685,45.085 22.86,45.085 46.355,46.355 48.26,47.625 31.75,48.26 2.54,48.641 17.78,51.435 20.32,51.435 22.86,51.435 22.86,53.975 31.115,53.975
  other v2: 6.35,3.81 32.004,6.096 3.81,6.35 6.35,6.35 8.89,6.35 11.43,6.35 28.067,7.188 3.81,13.97 3.81,19.05 6.35,19.05 8.89,19.05 3.81,21.59 10.16,27.94 38.71,28.397 2.54,33.528 5.08,33.528 7.62,33.528 10.16,33.528 7.62,44.45 7.62,46.99 10.16,52.07 12.7,53.34
IIC1_SCL: R6.1 U3.6 U6.42 | length 16.3
  Top Layer w0.203: R6.1@16.129,27.762 R6.1 16.129,23.901 17.043,22.987 U3.6 24.714,22.987 v1(24.968,22.733)
  Bottom Layer w0.203: v1(24.968,22.733) 26.09,21.611 U6.42
IIC1_SDA: R7.1 U3.5 U6.43 | length 21.7
  Top Layer w0.203: R7.1@16.129,29.947 14.91,28.727 14.91,23.52 16.713,21.717 U3.5 21.666,21.717 v1(24.689,18.694)
  Bottom Layer w0.203: v1(24.689,18.694) 26.06,18.694 26.59,19.224 U6.43
IN1: U6.15 U12.2 | length 14.1
  Bottom Layer w0.203: U6.15 28.09,10.061 29.108,9.042 35.255,9.042 38.481,12.268 U12.2
IN2: U6.14 U13.2 | length 18.1
  Bottom Layer w0.203: U6.14 28.59,10.268 29.214,9.644 35.044,9.644 36.855,11.455 36.855,16.485 37.668,17.297 U13.2
LED: R19.2 U6.29 | length 6.2
  Top Layer w0.203: R19.2 v1(17.704,14.199)
  Bottom Layer w0.203: v1(17.704,14.199) 18.579,15.074 U6.29
M1_1: C32.2 J8.1 Q5.1 Q8.1 R38.1
  other v2: 50.8,42.672 52.324,42.672 53.848,42.672 55.372,42.672 50.8,44.196 52.324,44.196 53.848,44.196 55.372,44.196 50.8,45.72 52.324,45.72 53.848,45.72 55.372,45.72 50.8,47.244 52.324,47.244 53.848,47.244 55.372,47.244 50.8,48.768 52.324,48.768 53.848,48.768 55.372,48.768
M1_2: C33.2 J8.2 Q4.1 Q7.1 R40.1 | length 5
  Bottom Layer w0.6: J8.2 J8.2 R40.1 C33.2
NetC1_1: C1.1 U1.8 | length 3.9
  Top Layer w0.6: C1.1 36.195,32.944 36.805,32.334 U1.8
NetC1_2: C1.2 D1.2 L1.1 U1.1 | length 1
  Top Layer w0.6: L1.1@33.785,24.409 L1.1@33.807,24.432 ; U1.1 U1.1@36.805,26.568
NetC3_1: C3.1 C7.1 F1.2 R1.2 U1.7 | length 26.6
  Top Layer w0.6: v2(35.789,22.911) 35.789,21.869 R1.2 ; U1.7 v2(38.075,33.934) C7.1 39.079,37.581 C3.1 F1.2
  Bottom Layer w0.6: v2(35.789,22.911) 37.465,24.587 37.465,28.946 38.075,29.556 v2(38.075,33.934)
NetC8_2: C8.2 C9.2 C12.1 FB1.1 U2.0 U2.2 | length 16.9
  Top Layer w0.6: U2.0 U2.2 21.438,38.913 21.996,38.354 C9.2 FB1.1
NetC11_1: C11.1 U1.3 | length 2.8
  Top Layer w0.203: C11.1@39.345,22.758 U1.3
NetC11_2: C11.2 R5.2 | length 2.2
  Top Layer w0.203: C11.2@39.395,20.422 R5.2@41.605,20.422
NetC18_1: C18.1 R8.1 U5.7 | length 8
  Top Layer w0.203: U5.7 3.988,40.894 C18.1 R8.1
NetC18_2: C18.2 R20.1 U5.8 | length 7.6
  Top Layer w0.203: U5.8 C18.2 R20.1
NetC19_1: C19.1 R9.1 U5.9 | length 7.3
  Top Layer w0.203: R9.1@2.718,23.444 2.718,25.603 U5.9
NetC19_2: C19.2 R21.1 U5.10 | length 8.1
  Top Layer w0.203: U5.10 3.988,26.645 C19.2 R21.1
NetC21_2: C21.2 FB2.1 U9.1 | length 5.9
  Top Layer w0.6: C21.2 56.109,15.316 56.363,15.062 FB2.1 58.572,15.088 U9.1
NetD5_2: D5.2 Q2.1 R13.2 | length 5.4
  Top Layer w0.6: Q2.1 52.602,12.991 54.319,12.991 54.331,12.979 R13.2@54.331,10.49
NetD8_1: D8.1 R24.2 U7.4 U7.5 U8.2 U8.4 | length 32.3
  Top Layer w0.203: D8.1 v1(60.376,17.831)
  Bottom Layer w0.203: U7.4 U7.5 52.476,29.82 53.264,30.607 58.547,30.607 59.258,29.896 U8.2 59.258,26.619 ; v1(60.376,17.831) 59.842,17.297 R24.2 57.048,18.186 57.048,24.409 59.258,26.619 ; U8.4 61.798,26.619 61.443,26.264 59.614,26.264 59.258,26.619
NetD8_2: D8.2 U9.2 | length 2.8
  Top Layer w0.6: U9.2 58.572,18.745 D8.2
NetD10_1: D10.1 R30.2 U11.3 | length 4.5
  Bottom Layer w0.203: U11.3 R30.2 D10.1
NetD10_2: D10.2 R12.1 R29.1 | length 4.5
  Bottom Layer w0.203: R12.1 48.819,2.464 D10.2 R29.1
NetD11_1: D11.1 Q6.2 R31.2 | length 3.9
  Top Layer w0.6: D11.1@55.855,8.407 Q6.2 R31.2
NetD12_1: D12.1 R34.2 R36.1 U8.1 U12.3 | length 30.9
  Top Layer w0.203: v1(49.53,11.303) 49.53,12.7 49.428,12.802 49.428,24.689 50.317,25.578 57.15,25.578 v1(57.988,26.416)
  Bottom Layer w0.203: U12.3 R34.2 D12.1 R36.1 ; v1(57.988,26.416) U8.1
NetD12_2: D12.2 D13.2 R23.2 R24.1 | length 11.6
  Bottom Layer w0.203: D12.2 53.365,13.462 53.924,14.021 55.626,14.021 55.905,14.3 55.905,17.043 R24.1 D13.2 R23.2
NetD13_1: D13.1 R39.2 R43.1 U8.5 U13.3 | length 39.3
  Bottom Layer w0.203: R43.1 D13.1 R39.2 U13.3 45.314,29.362 47.117,31.166 61.697,31.166 63.068,29.794 U8.5
NetF2_1: F2.1 Q2.2 | length 4.8
  Top Layer w0.6: 45.264,10.491 Q2.2@45.264,15.291
NetLED1_1: LED1.1 R19.1 | length 2.3
  Top Layer w0.203: LED1.1@15.418,10.48 R19.1
NetQ1_2: Q1.2 U5.2 | length 12.6
  Top Layer w0.203: U5.2 10.338,38.964 11.151,39.776 14.961,39.776 16.688,41.504 Q1.2
NetQ3_1: Q3.1 R29.2 | length 3.1
  Bottom Layer w0.203: R29.2 Q3.1
NetQ3_3: Q3.3 R26.1 R27.2 | length 4.9
  Bottom Layer w0.203: Q3.3 R27.2 R26.1
NetQ9_1: Q9.1 R36.2 | length 3.2
  Bottom Layer w0.203: R36.2 Q9.1
NetQ9_3: Q9.3 R33.1 R35.2 | length 4.8
  Bottom Layer w0.203: Q9.3 R35.2 R33.1
NetQ10_1: Q10.1 R43.2 | length 3.2
  Bottom Layer w0.203: R43.2 Q10.1
NetQ10_3: Q10.3 R41.1 R42.2 | length 4.9
  Bottom Layer w0.203: Q10.3 R42.2 R41.1
NetR1_1: R1.1 U1.2 | length 3.2
  Top Layer w0.203: R1.1 38.075,23.546 U1.2
NetR2_2: R2.2 R3.2 U1.4 | length 4.6
  Top Layer w0.6: U1.4 R3.2 R2.2
NetR4_2: R4.2 U1.6 | length 4.3
  Top Layer w0.6: U1.6 39.345,32.944 39.903,33.503 R4.2
NetR11_1: R11.1 U4.2 U4.3 | length 7.4
  Bottom Layer w0.203: U4.3 U4.2 14.249,32.944 14.478,33.172 16.561,33.172 17.221,32.512 R11.1
NetR12_2: R12.2 U7.6 | length 44.9
  Top Layer w0.203: v1(53.746,29.972) v1(53.746,32.106)
  Bottom Layer w0.203: R12.2 43.79,2.464 41.758,4.496 41.758,16.002 44.729,18.974 44.729,29.693 47.142,32.106 v1(53.746,32.106) ; U7.6 v1(53.746,29.972)
NetR17_1: R17.1 R18.1 U5.4 | length 10.4
  Top Layer w0.203: U5.4 7.798,39.345 9.169,40.716 11.176,40.716 R17.1 R18.1
NetR26_2: R26.2 U10.2 U10.4 | length 36.7
  Top Layer w0.203: v1@62.662,7.188 62.662,19.126 72.415,28.88 v1(72.415,30.048)
  Bottom Layer w0.203: R26.2 61.265,5.664 62.382,5.664 62.662,5.944 v1(62.662,6.934) ; U10.2 69.875,26.899 70.079,26.695 72.161,26.695 72.415,26.949 U10.4 v1(72.415,30.048)
NetR28_2: R28.2 U11.1 | length 17.4
  Bottom Layer w0.203: U11.1 39.37,4.699 41.123,6.452 41.123,17.145 43.663,19.685 R28.2
NetR32_2: R32.2 U12.1 | length 11.7
  Bottom Layer w0.203: U12.1 39.421,9.728 40.513,10.82 40.513,17.272 41.885,18.644 R32.2
NetR33_2: R33.2 U10.1 | length 24.9
  Top Layer w0.203: v1(61.239,11.227) 61.976,11.963 61.976,19.279 68.605,25.908 v1(68.605,30.048)
  Bottom Layer w0.203: R33.2 v1(61.239,11.227) ; U10.1 v1(68.605,30.048)
NetR37_2: R37.2 U13.1 | length 6
  Bottom Layer w0.203: U13.1 39.472,14.757 40.107,15.392 R37.2
NetR41_2: R41.2 U10.5 | length 21.2
  Top Layer w0.203: v1(63.322,14.935) 63.322,18.771 71.374,26.822 v1(73.685,26.822)
  Bottom Layer w0.203: R41.2 v1(63.322,14.935) ; v1(73.685,26.822) U10.5
NetR44_1: R44.1 U6.10 U14.1 | length 26
  Top Layer w0.203: v1(26.797,28.931) 26.797,21.692 28.372,20.117 v1(28.372,16.688)
  Bottom Layer w0.203: v1(26.797,28.931) 26.797,32.207 27.254,32.664 U14.1 R44.1 ; v1(28.372,16.688) 28.372,15.164 29.461,14.074 U6.10
NetR44_2: R44.2 R45.1 U14.2 | length 7.8
  Bottom Layer w0.203: U14.2 33.223,31.394 R44.2 R45.1
NetR46_1: R46.1 U14.3 | length 3.2
  Bottom Layer w0.203: U14.3 R46.1
NRST: C15.2 R15.1 U6.7 | length 4
  Top Layer w0.203: R15.1 29.286,14.834 v1(29.286,15.824) 29.286,16.815 C15.2
  Bottom Layer w0.203: v1(29.286,15.824) 29.536,15.574 U6.7
OSC1: C23.2 U6.5 Y1.2 | length 7.7
  Top Layer w0.203: Y1.2 35.687,17.45 C23.2
  Bottom Layer w0.203: U6.5 31.814,16.574 32.69,17.45 Y1.2
OSC2: C24.2 U6.6 Y1.1 | length 10.1
  Top Layer w0.203: Y1.1 36.017,12.37 C24.2
  Bottom Layer w0.203: U6.6 32.592,16.074 33.858,14.808 Y1.1
REFER: C22.2 C31.1 D7.1 Q6.3 U10.7 | length 43.4
  Top Layer w0.6: D7.1@56.363,4.369 54.331,4.369 54.331,6.299 54.534,6.502 Q6.3 58.217,5.944 63.297,5.944 64.237,6.883 64.237,18.415 71.476,25.654 v2(76.225,25.654)
  Bottom Layer w0.6: 76.225,26.06 U10.7
RS485_A: D3.2 J1.1 J2.1 R10.2 U4.6 | length 53.8
  Bottom Layer w0.203: U4.6 12.979,47.32 15.138,49.479 24.333,49.479 26.441,51.587 R10.2 26.441,55.347 J2.1 27,58.242 45.136,58.242 J1.1
RS485_B: D2.1 J1.2 J2.2 R10.1 U4.7 | length 57.6
  Top Layer w0.203: J2.2 31.953,58.115 50.114,58.115 51.714,56.515 J1.2
  Bottom Layer w0.203: U4.7 14.249,47.65 15.469,48.87 28.054,48.87 D2.1 28.727,51.931 R10.1@28.727,53.442 ; R10.1@28.727,53.111 R10.1@28.727,53.442 ; J2.2 28.727,54.889 R10.1 R10.1@28.727,53.442
SENSOR: Q7.3 Q8.3 R46.2 R48.2 | length 45
  Top Layer w0.203: Q7.3@65.507,34.375 Q7.3
  Top Layer w4: 60.706,39.37 60.833,39.243 61.468,38.608 61.785,38.291 v2(62.431,37.645) 62.738,37.338 63.055,37.02 v2(63.512,36.564) 64.008,36.068 64.325,35.75 v2(64.516,35.56) 65.024,35.052
  Bottom Layer w0.203: R46.2 35.814,31.445 35.814,34.915 39.888,38.989 R48.2@42.848,38.989 ; R48.2@42.848,38.479 R48.2@42.848,38.989 ; R48.2 R48.2@42.848,38.989
  Bottom Layer w4: 44.018,38.989 60.96,38.989 ; v2@61.485,38.591 61.468,38.608 v2@61.366,38.608 ; v2@63.246,36.83 v2(63.512,36.564) ; v2@63.754,36.322 64.008,36.068 ; v2@64.262,35.814 64.008,36.068 ; 60.96,38.989 v2@61.366,38.608 ; 60.96,38.989 61.341,38.608 v2@61.366,38.608 ; v2@61.366,38.608 61.424,38.553 61.721,38.275 62.413,37.624 62.753,37.305 63.029,37.045 63.055,37.02 v2(63.512,36.564) ; v2(63.512,36.564) 64.008,36.068
  other v2: 63.5,34.925 62.23,36.195 64.77,36.83 60.96,37.465 63.5,38.1 61.595,38.735 61.595,40.005
SENSOR_A+: J4.1 R20.2 | length 11.2
  Top Layer w0.203: R20.2 5.486,49.378 5.486,53.032 J4.1
SENSOR_A-: J4.2 R8.2 | length 12.6
  Top Layer w0.203: R8.2 5.944,47.549 5.944,50.723 10.847,55.626 J4.2
SENSOR_B+: R21.2
SENSOR_B-: R9.2
SENSOR_DOUT: U5.12 U6.18 | length 34.4
  Top Layer w0.203: U5.12 6.528,28.143 7.036,27.635 8.204,27.635 9.728,26.111 9.728,22.123 10.795,21.057 21.412,21.057 25.476,16.993 v1(25.476,14.275)
  Bottom Layer w0.203: v1(25.476,14.275) 25.476,13.818 26.59,12.704 U6.18
SENSOR_E+: C16.2 J4.4 Q1.1 R17.2 U5.3 | length 28.5
  Top Layer w0.203: U5.3 9.068,39.141 10.185,40.259 13.005,40.259 R17.2 Q1.1 13.843,46.228 C16.2 12.37,49.229 18.767,55.626 J4.4
SENSOR_SCK: U5.11 U6.19 | length 35.1
  Top Layer w0.203: U5.11 5.258,28.55 6.655,27.153 7.925,27.153 9.246,25.832 9.246,21.793 10.414,20.625 21.26,20.625 24.867,17.018 v1(24.867,13.462)
  Bottom Layer w0.203: v1(24.867,13.462) 25.197,13.462 26.09,12.569 U6.19
SW1: S1.1 U6.46 | length 35.9
  Top Layer w0.203: S1.1 v1(3.302,9.423)
  Bottom Layer w0.203: v1(3.302,9.423) 3.302,12.062 15.07,23.83 25.598,23.83 28.09,21.339 U6.46
SW2: S1.2 U6.45 | length 33.9
  Top Layer w0.203: S1.2 v1(4.572,9.423)
  Bottom Layer w0.203: v1@4.572,9.449 4.572,12.595 15.327,23.351 25.367,23.351 27.59,21.127 U6.45
SW3: S1.3 U6.41 | length 30.3
  Top Layer w0.203: S1.3 v1(5.842,9.423)
  Bottom Layer w0.203: v1(5.842,9.423) 5.842,13.12 15.227,22.504 24.257,22.504 25.59,21.172 U6.41
SW4: S1.4 U6.40 | length 28.5
  Top Layer w0.203: S1.4 v1(7.112,9.423)
  Bottom Layer w0.203: v1(7.112,9.423) 7.112,13.682 15.502,22.073 24.105,22.073 25.09,21.087 U6.40
SW5: S1.5 U6.39 | length 26.6
  Top Layer w0.203: S1.5 v1(8.382,9.423)
  Bottom Layer w0.203: v1(8.382,9.423) 8.382,14.245 15.777,21.641 23.952,21.641 24.59,21.003 U6.39
SW6: S1.6 U6.38 | length 24.8
  Top Layer w0.203: S1.6 v1(9.652,9.423)
  Bottom Layer w0.203: 9.65,13.159 9.652,13.16 ; v1@9.652,9.449 9.652,13.16 ; U6.38 24.09,20.906 23.787,21.209 16.053,21.209 9.652,14.808 9.652,13.16
SW7: S1.7 U6.33 | length 17.2
  Top Layer w0.203: S1.7 v1(10.922,9.423)
  Bottom Layer w0.203: v1(10.922,9.423) 10.922,12.09 15.906,17.074 U6.33
SW8: S1.8 U6.32 | length 17.1
  Top Layer w0.203: S1.8 v1(12.192,9.423)
  Bottom Layer w0.203: 12.192,10.414 v1(12.192,9.423) 12.192,12.751 16.015,16.574 U6.32
SWCLK: J5.3 U6.37 | length 28.9
  Top Layer w0.203: J5.3@11.633,1.549 13.437,3.353 13.437,18.517 15.011,20.091 20.777,20.091 v1(21.26,19.609)
  Bottom Layer w0.203: v1(21.26,19.609) 21.725,20.074 U6.37
SWDIO: J5.2 U6.34 | length 23.4
  Top Layer w0.203: J5.2@14.173,1.549 v1(14.173,16.612)
  Bottom Layer w0.203: v1(14.173,16.612) 15.136,17.574 U6.34
SWITCH_21: Q5.2 U10.3 | length 23
  Top Layer w0.203: Q5.2 62.518,41.427 66.827,41.427 68.047,40.208 68.047,33.35 v1(71.145,30.251)
  Bottom Layer w0.203: U10.3 v1(71.145,30.251)
SWITCH_22: Q8.2 U8.3 | length 7.2
  Top Layer w0.203: Q8.2 59.815,30.711 v1(60.528,29.997)
  Bottom Layer w0.203: U8.3 v1(60.528,29.997)
SWITCH_23: Q4.2 U10.6 | length 25.9
  Top Layer w0.203: Q4.2 68.504,46.448 68.504,33.909 71.704,30.709 v1(74.955,30.709)
  Bottom Layer w0.203: U10.6 v1(74.955,30.709)
SWITCH_24: Q7.2 U8.6 | length 13.1
  Top Layer w0.203: v1@66.195,38.077 Q7.2
  Bottom Layer w0.203: U8.6 64.338,29.997 67.183,32.842 67.183,37.084 v1(66.192,38.075)
UART1_RX: J6.1 U6.31 | length 24
  Top Layer w0.203: v1(23.419,16.332) 24.232,15.519 24.232,8.407 28.829,3.81 34.29,3.81 J6.1
  Bottom Layer w0.203: U6.31 23.161,16.074 v1(23.419,16.332)
UART1_TX: J6.2 U6.30 | length 20.8
  Top Layer w0.203: v1(23.571,15.164) 23.571,8.433 28.702,3.302 32.258,3.302 J6.2
  Bottom Layer w0.203: U6.30 23.161,15.574 v1(23.571,15.164)
VBG: C17.1 U5.6 | length 6.1
  Top Layer w0.203: U5.6 5.258,38.252 7.544,40.538 C17.1
VDD: C21.1 C30.1 D9.2 Q2.3 U7.14 U8.14 U9.3 U11.4 U12.4 U13.4 | length 45.7
  Top Layer w0.6: v2(50.216,13.716) 50.216,16.043 51.764,17.591 ; C30.1@51.764,20.607 51.764,17.591 ; D9.2 57.429,23.393 v1(57.988,23.952) ; U9.3@56.529,17.591 51.764,17.591
  Bottom Layer w0.4: U11.4 44.094,4.699 43.739,5.055 43.739,9.195 44.272,9.728 ; U12.4 44.272,9.728 ; v2(50.216,13.716) 46.787,13.716 45.745,14.757 44.196,14.757 43.764,14.326 43.764,10.236 44.272,9.728
  Bottom Layer w0.6: U7.14 47.396,24.028 48.133,24.765 50.241,24.765 v2(50.952,24.054) ; U8.14 v1(57.988,23.952)
pads on no net: U3.1 U3.2 U3.3 U3.7 U5.13 U6.2 U6.3 U6.4 U6.17 U6.25 U6.26 U6.27 U6.28 U7.1 U7.2 U7.3 U7.8 U7.9 U7.10 U7.11 U7.12 U7.13 U8.8 U8.9 U8.10 U8.11 U8.12 U8.13 U10.8 U10.9 U10.10 U10.11 U10.12 U10.13 U14.5 U14.6 U14.7

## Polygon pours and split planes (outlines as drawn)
GND on Top Layer "Top Layer-No Net" (solid, remove dead copper, pour order 1000): 0,60 0,0 80,0 80,60
GND on Bottom Layer "Top Layer-No Net" (solid, remove dead copper, pour order 1001): 0,60 0,0 80,0 80,60

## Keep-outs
Keep-Out Layer:
  the board outline again, w0.127

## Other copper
Top Layer:
  rectangle net VDD: 50.521,16.866 52.959,24.486
  rectangle net GND: 44.425,19.228 48.006,26.264
  rectangle net M1_2: 69.113,34.112 76.276,49.708
  rectangle net M1_1: 49.682,34.188 56.896,49.657
  rectangle net NetC1_2: 33.376,24.333 37.084,26.848
  rectangle net GND: 32.639,36.83 36.5,57.76
  rectangle net GND: 26.645,34.595 35.23,39.091
  rectangle net GND: 27.737,31.801 29.286,38.176
  rectangle net GND: 54.483,54.737 59.309,58.293
  region net M1_2: 70.764,56.49 70.764,53.137 69.113,51.486 69.113,47.777 76.276,47.777 76.276,51.511 73.254,54.534 73.254,56.49 72.619,57.125 71.577,57.125
  region net NetC1_2: 35.306,23.647 33.325,23.647 33.325,27.559 30.81,30.074 30.81,31.445 34.925,31.445 35.306,31.064
  pour cut-out: 27.33,28.626 27.381,28.677 35.306,28.677 35.306,23.647 35.281,23.673 35.255,23.114 27.33,23.114
Bottom Layer:
  rectangle net GND: 32.664,37.313 37.211,57.785
  rectangle net +24V: 38.456,42.647 43.967,57.734
  rectangle net +24V: 60.655,50.216 63.602,58.268
  rectangle net +24V: 38.481,50.19 63.602,54.178
  rectangle net GND: 54.483,54.864 59.309,58.293
  region net M1_1: 67.285,56.921 66.472,56.109 66.472,49.784 66.065,49.479 63.957,49.505 49.733,49.505 49.733,42.113 49.708,42.088 49.759,42.037 63.576,42.037 69.367,47.828 69.367,56.134 68.58,56.921

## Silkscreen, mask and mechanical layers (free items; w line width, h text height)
Top Overlay:
  text "+24V" at 38.989,52.451 h1
  text "485A" at 23.622,52.324 h1
  text "485B" at 28.575,52.324 h1
  text "GND" at 34.29,52.324 h1
  text "485A" at 44.958,52.324 h1
  text "485B" at 50.038,52.324 h1
  text "GND" at 55.88,52.324 h1
  text "+24V" at 60.071,52.324 h1
  text "A+" at 5.969,48.87 h1
  text "A-" at 9.982,48.87 h1
  text "E-" at 13.995,48.87 h1
  text "E+" at 18.009,48.87 h1
  text "YarnControl_Driver_v1.1" at 53.061,27.864 h1
  text "2018.10.31" at 60.579,26.289 h1
  text "GND" at 7.747,4.064 h1
  text "CLK" at 10.795,4.064 h1
  text "IO" at 13.843,4.064 h1
  text "3.3" at 15.875,4.064 h1
  text "RX" at 19.05,4.064 h1
  text "TX" at 21.463,4.064 h1
  text "GND" at 23.622,4.064 h1
  text "3.3" at 26.67,4.064 h1
  text "GND" at 29.845,4.064 h1
  text "TX" at 32.893,4.064 h1
  text "RX" at 35.179,4.064 h1
Top Solder:
  lines w3: 59.815,39.638 60.565,39.638 65.14,35.063 66.195,35.063 ; 59.815,50.802 59.815,48.796 64.454,44.157 66.195,44.157

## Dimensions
0,0 to 0,60 on Top Overlay
0,0 to 80,0 on Top Overlay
